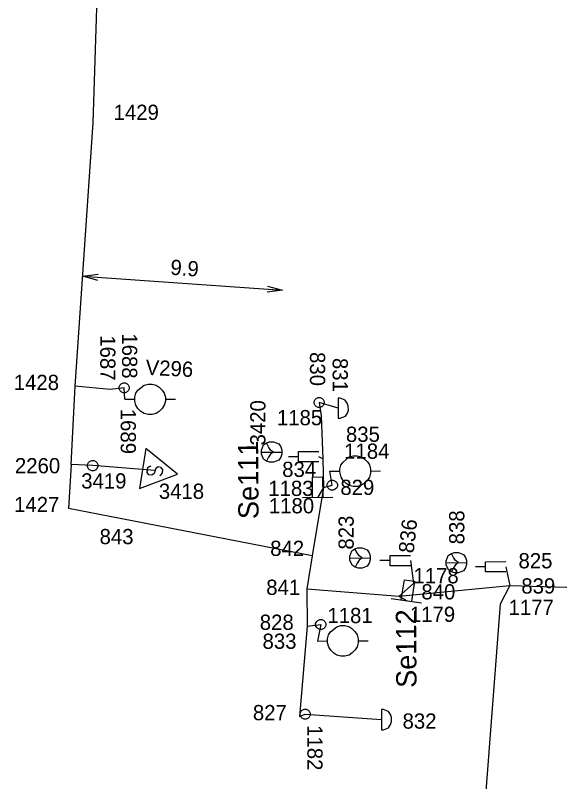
# Model space of a CAD drawing. Extents: x -535557 to -534097, y -1142175 to -1136716.
# Drawn here: x -534486.47 to -534459.64, y -1141039.91 to -1141002.16 of the extents above; entities that cross this region are included whole.
import ezdxf

# ---------------------------------------------------------------- set-up
doc = ezdxf.new("R2010")
doc.units = 0
doc.layers.add('Default', color=7, linetype='Continuous')
doc.layers.add('SS_SZDC', color=7, linetype='Continuous')

# ---------------------------------------------------------------- blocks, each defined once
blk = doc.blocks.new('POINT_DISPLAY')
at = {"layer": 'Default'}
blk.add_line((0, 0), (0, 0), dxfattribs=at)

msp = doc.modelspace()

# ---------------------------------------------------------------- linework, layer by layer
at = {"layer": 'SS_SZDC'}
for p, q in [((-534482.63, -1141007.459), (-534482.289, -1140996.2)), ((-534483.52, -1141020.42), (-534482.63, -1141007.459)), ((-534483.148, -1141015.012), (-534482.39, -1141014.914)), ((-534483.148, -1141015.012), (-534473.301, -1141015.695)), ((-534482.41, -1141015.213), (-534483.148, -1141015.012)), ((-534474.039, -1141015.493), (-534473.301, -1141015.695)), ((-534473.301, -1141015.695), (-534474.06, -1141015.793)), ((-534483.719, -1141024.29), (-534483.52, -1141020.42)), ((-534481.8, -1141020.59), (-534483.52, -1141020.42)), ((-534481.109, -1141020.51), (-534481.8, -1141020.59)), ((-534481.359, -1141020.46), (-534481.309, -1141020.36)), ((-534481.359, -1141020.56), (-534481.359, -1141020.46)), ((-534481.309, -1141020.66), (-534481.359, -1141020.56)), ((-534481.309, -1141020.36), (-534481.259, -1141020.31)), ((-534481.259, -1141020.31), (-534481.159, -1141020.26)), ((-534481.159, -1141020.26), (-534481.059, -1141020.26)), ((-534481.079, -1141021.069), (-534481.109, -1141020.51)), ((-534481.059, -1141020.26), (-534480.959, -1141020.31)), ((-534480.959, -1141020.31), (-534480.909, -1141020.36)), ((-534480.909, -1141020.36), (-534480.859, -1141020.46)), ((-534480.859, -1141020.56), (-534480.909, -1141020.66)), ((-534480.859, -1141020.46), (-534480.859, -1141020.56)), ((-534480.429, -1141020.619), (-534480.129, -1141020.369)), ((-534480.129, -1141020.369), (-534479.929, -1141020.319)), ((-534479.929, -1141020.319), (-534479.729, -1141020.319)), ((-534479.729, -1141020.319), (-534479.529, -1141020.369)), ((-534479.529, -1141020.369), (-534479.379, -1141020.469)), ((-534479.379, -1141020.469), (-534479.229, -1141020.619)), ((-534481.259, -1141020.71), (-534481.309, -1141020.66)), ((-534481.159, -1141020.76), (-534481.259, -1141020.71)), ((-534481.059, -1141020.76), (-534481.159, -1141020.76)), ((-534480.959, -1141020.71), (-534481.059, -1141020.76)), ((-534480.909, -1141020.66), (-534480.959, -1141020.71)), ((-534480.579, -1141020.969), (-534480.529, -1141020.769)), ((-534480.579, -1141021.069), (-534480.579, -1141020.969)), ((-534480.529, -1141020.769), (-534480.429, -1141020.619)), ((-534479.229, -1141020.619), (-534479.129, -1141020.769)), ((-534479.129, -1141020.769), (-534479.079, -1141020.969)), ((-534479.079, -1141020.969), (-534479.079, -1141021.169)), ((-534471.65, -1141021.029), (-534471.55, -1141020.979)), ((-534471.55, -1141020.979), (-534471.449, -1141020.979)), ((-534471.449, -1141020.979), (-534471.349, -1141021.029)), ((-534481.079, -1141021.069), (-534480.579, -1141021.069)), ((-534480.579, -1141021.169), (-534480.579, -1141021.069)), ((-534480.529, -1141021.369), (-534480.579, -1141021.169)), ((-534479.079, -1141021.169), (-534479.129, -1141021.369)), ((-534479.079, -1141021.069), (-534478.579, -1141021.069)), ((-534471.75, -1141021.179), (-534471.699, -1141021.079)), ((-534471.75, -1141021.279), (-534471.75, -1141021.179)), ((-534471.699, -1141021.379), (-534471.75, -1141021.279)), ((-534471.699, -1141021.079), (-534471.65, -1141021.029)), ((-534470.56, -1141021.51), (-534471.5, -1141021.229)), ((-534471.5, -1141021.229), (-534471.399, -1141021.899)), ((-534471.349, -1141021.029), (-534471.3, -1141021.079)), ((-534471.3, -1141021.079), (-534471.25, -1141021.179)), ((-534471.25, -1141021.279), (-534471.3, -1141021.379)), ((-534471.25, -1141021.179), (-534471.25, -1141021.279)), ((-534470.463, -1141021.009), (-534470.563, -1141021.01)), ((-534470.563, -1141021.01), (-534470.556, -1141022.009)), ((-534470.212, -1141021.107), (-534470.463, -1141021.009)), ((-534470.111, -1141021.257), (-534470.212, -1141021.107)), ((-534470.06, -1141021.406), (-534470.111, -1141021.257)), ((-534480.429, -1141021.519), (-534480.529, -1141021.369)), ((-534480.279, -1141021.669), (-534480.429, -1141021.519)), ((-534480.129, -1141021.769), (-534480.279, -1141021.669)), ((-534479.379, -1141021.669), (-534479.529, -1141021.769)), ((-534479.229, -1141021.519), (-534479.379, -1141021.669)), ((-534479.129, -1141021.369), (-534479.229, -1141021.519)), ((-534471.65, -1141021.429), (-534471.699, -1141021.379)), ((-534471.55, -1141021.479), (-534471.65, -1141021.429)), ((-534471.449, -1141021.479), (-534471.55, -1141021.479)), ((-534471.349, -1141021.429), (-534471.449, -1141021.479)), ((-534471.3, -1141021.379), (-534471.349, -1141021.429)), ((-534470.108, -1141021.757), (-534470.059, -1141021.606)), ((-534470.059, -1141021.606), (-534470.06, -1141021.406)), ((-534479.929, -1141021.819), (-534480.129, -1141021.769)), ((-534479.729, -1141021.819), (-534479.929, -1141021.819)), ((-534479.529, -1141021.769), (-534479.729, -1141021.819)), ((-534471.399, -1141021.899), (-534471.31, -1141024.01)), ((-534470.556, -1141022.009), (-534470.456, -1141022.009)), ((-534470.456, -1141022.009), (-534470.207, -1141021.907)), ((-534470.207, -1141021.907), (-534470.108, -1141021.757)), ((-534474.24, -1141023.32), (-534474.09, -1141023.22)), ((-534474.09, -1141023.22), (-534473.94, -1141023.17)), ((-534473.99, -1141023.42), (-534474.09, -1141023.22)), ((-534473.94, -1141023.17), (-534473.74, -1141023.17)), ((-534473.74, -1141023.17), (-534473.49, -1141023.27)), ((-534480.046, -1141023.498), (-534480.359, -1141025.473)), ((-534478.474, -1141024.759), (-534480.046, -1141023.498)), ((-534474.34, -1141023.57), (-534474.24, -1141023.32)), ((-534474.34, -1141023.77), (-534474.34, -1141023.57)), ((-534473.89, -1141023.57), (-534473.99, -1141023.42)), ((-534473.74, -1141023.67), (-534473.89, -1141023.57)), ((-534473.49, -1141023.27), (-534473.39, -1141023.42)), ((-534473.39, -1141023.42), (-534473.34, -1141023.57)), ((-534473.34, -1141023.57), (-534473.34, -1141023.77)), ((-534474.34, -1141023.67), (-534473.34, -1141023.67)), ((-534474.24, -1141024.02), (-534474.34, -1141023.77)), ((-534473.99, -1141023.92), (-534474.09, -1141024.12)), ((-534473.89, -1141023.77), (-534473.99, -1141023.92)), ((-534473.74, -1141023.67), (-534473.89, -1141023.77)), ((-534473.39, -1141023.92), (-534473.49, -1141024.07)), ((-534473.34, -1141023.77), (-534473.39, -1141023.92)), ((-534472.51, -1141023.899), (-534473.01, -1141023.899)), ((-534472.51, -1141024.149), (-534472.51, -1141023.649)), ((-534472.51, -1141023.649), (-534471.51, -1141023.649)), ((-534471.31, -1141024.01), (-534471.51, -1141023.899)), ((-534470.322, -1141024.165), (-534470.024, -1141023.913)), ((-534470.024, -1141023.913), (-534469.824, -1141023.862)), ((-534469.824, -1141023.862), (-534469.624, -1141023.861)), ((-534469.624, -1141023.861), (-534469.424, -1141023.909)), ((-534469.424, -1141023.909), (-534469.273, -1141024.008)), ((-534483.719, -1141024.29), (-534483.859, -1141026.459)), ((-534482.659, -1141024.34), (-534483.719, -1141024.29)), ((-534482.909, -1141024.29), (-534482.859, -1141024.19)), ((-534482.909, -1141024.39), (-534482.909, -1141024.29)), ((-534482.859, -1141024.19), (-534482.809, -1141024.14)), ((-534482.809, -1141024.14), (-534482.709, -1141024.09)), ((-534482.709, -1141024.09), (-534482.609, -1141024.09)), ((-534479.609, -1141024.579), (-534482.659, -1141024.34)), ((-534482.609, -1141024.09), (-534482.509, -1141024.14)), ((-534482.509, -1141024.14), (-534482.459, -1141024.19)), ((-534482.459, -1141024.19), (-534482.409, -1141024.29)), ((-534482.409, -1141024.29), (-534482.409, -1141024.39)), ((-534479.882, -1141024.384), (-534479.776, -1141024.351)), ((-534474.09, -1141024.12), (-534474.24, -1141024.02)), ((-534473.94, -1141024.17), (-534474.09, -1141024.12)), ((-534473.74, -1141024.17), (-534473.94, -1141024.17)), ((-534473.49, -1141024.07), (-534473.74, -1141024.17)), ((-534471.51, -1141024.149), (-534472.51, -1141024.149)), ((-534471.31, -1141024.01), (-534471.289, -1141025.409)), ((-534470.47, -1141024.516), (-534470.421, -1141024.316)), ((-534470.421, -1141024.316), (-534470.322, -1141024.165)), ((-534469.273, -1141024.008), (-534469.122, -1141024.157)), ((-534469.122, -1141024.157), (-534469.022, -1141024.307)), ((-534469.022, -1141024.307), (-534468.97, -1141024.506)), ((-534482.859, -1141024.49), (-534482.909, -1141024.39)), ((-534482.809, -1141024.54), (-534482.859, -1141024.49)), ((-534482.709, -1141024.59), (-534482.809, -1141024.54)), ((-534482.609, -1141024.59), (-534482.709, -1141024.59)), ((-534482.509, -1141024.54), (-534482.609, -1141024.59)), ((-534482.459, -1141024.49), (-534482.509, -1141024.54)), ((-534482.409, -1141024.39), (-534482.459, -1141024.49)), ((-534479.979, -1141024.673), (-534479.94, -1141024.426)), ((-534479.896, -1141024.787), (-534479.979, -1141024.673)), ((-534479.94, -1141024.426), (-534479.882, -1141024.384)), ((-534479.633, -1141024.728), (-534479.747, -1141024.811)), ((-534479.544, -1141024.489), (-534479.633, -1141024.728)), ((-534479.43, -1141024.405), (-534479.544, -1141024.489)), ((-534479.282, -1141024.429), (-534479.43, -1141024.405)), ((-534479.287, -1141024.782), (-534479.222, -1141024.691)), ((-534479.199, -1141024.543), (-534479.282, -1141024.429)), ((-534479.222, -1141024.691), (-534479.199, -1141024.543)), ((-534470.97, -1141024.62), (-534470.47, -1141024.616)), ((-534470.85, -1141025.299), (-534470.97, -1141024.62)), ((-534470.47, -1141024.616), (-534470.47, -1141024.516)), ((-534470.469, -1141024.716), (-534470.47, -1141024.616)), ((-534470.418, -1141024.916), (-534470.469, -1141024.716)), ((-534468.969, -1141024.706), (-534469.018, -1141024.907)), ((-534468.97, -1141024.506), (-534468.969, -1141024.706)), ((-534468.97, -1141024.606), (-534468.47, -1141024.603)), ((-534480.359, -1141025.473), (-534478.474, -1141024.759)), ((-534479.747, -1141024.811), (-534479.896, -1141024.787)), ((-534479.344, -1141024.824), (-534479.287, -1141024.782)), ((-534471.826, -1141024.901), (-534471.326, -1141024.898)), ((-534471.819, -1141025.901), (-534471.826, -1141024.901)), ((-534471.326, -1141024.898), (-534471.32, -1141025.898)), ((-534471.05, -1141025.149), (-534471, -1141025.099)), ((-534471, -1141025.099), (-534470.9, -1141025.049)), ((-534470.9, -1141025.049), (-534470.8, -1141025.049)), ((-534470.8, -1141025.049), (-534470.7, -1141025.099)), ((-534470.7, -1141025.099), (-534470.65, -1141025.149)), ((-534470.317, -1141025.065), (-534470.418, -1141024.916)), ((-534470.166, -1141025.214), (-534470.317, -1141025.065)), ((-534469.117, -1141025.057), (-534469.266, -1141025.208)), ((-534469.018, -1141024.907), (-534469.117, -1141025.057)), ((-534471.289, -1141025.409), (-534471.84, -1141028.78)), ((-534471.289, -1141025.409), (-534471.569, -1141025.899)), ((-534471.289, -1141025.409), (-534470.85, -1141025.299)), ((-534471.1, -1141025.249), (-534471.05, -1141025.149)), ((-534471.1, -1141025.349), (-534471.1, -1141025.249)), ((-534471.05, -1141025.449), (-534471.1, -1141025.349)), ((-534471, -1141025.499), (-534471.05, -1141025.449)), ((-534470.9, -1141025.549), (-534471, -1141025.499)), ((-534470.7, -1141025.499), (-534470.8, -1141025.549)), ((-534470.65, -1141025.449), (-534470.7, -1141025.499)), ((-534470.65, -1141025.149), (-534470.6, -1141025.249)), ((-534470.6, -1141025.349), (-534470.65, -1141025.449)), ((-534470.6, -1141025.249), (-534470.6, -1141025.349)), ((-534470.015, -1141025.313), (-534470.166, -1141025.214)), ((-534469.815, -1141025.362), (-534470.015, -1141025.313)), ((-534469.615, -1141025.361), (-534469.815, -1141025.362)), ((-534469.415, -1141025.309), (-534469.615, -1141025.361)), ((-534469.266, -1141025.208), (-534469.415, -1141025.309)), ((-534470.8, -1141025.549), (-534470.9, -1141025.549)), ((-534472.319, -1141025.904), (-534470.82, -1141025.895)), ((-534481.819, -1141026.85), (-534483.859, -1141026.459)), ((-534471.84, -1141028.78), (-534481.819, -1141026.85)), ((-534469.882, -1141028.542), (-534469.732, -1141028.441)), ((-534469.732, -1141028.441), (-534469.583, -1141028.39)), ((-534469.631, -1141028.64), (-534469.732, -1141028.441)), ((-534469.583, -1141028.39), (-534469.383, -1141028.389)), ((-534469.383, -1141028.389), (-534469.132, -1141028.487)), ((-534469.132, -1141028.487), (-534469.031, -1141028.637)), ((-534471.84, -1141028.78), (-534472.1, -1141030.409)), ((-534469.98, -1141028.793), (-534469.882, -1141028.542)), ((-534469.979, -1141028.993), (-534469.98, -1141028.793)), ((-534469.979, -1141028.893), (-534468.98, -1141028.886)), ((-534469.53, -1141028.79), (-534469.631, -1141028.64)), ((-534469.38, -1141028.889), (-534469.53, -1141028.79)), ((-534469.38, -1141028.889), (-534469.529, -1141028.99)), ((-534469.031, -1141028.637), (-534468.98, -1141028.786)), ((-534468.98, -1141028.786), (-534468.979, -1141028.986)), ((-534468, -1141029.27), (-534468, -1141028.77)), ((-534468, -1141028.77), (-534467, -1141028.77)), ((-534465.23, -1141029.023), (-534465.132, -1141028.772)), ((-534465.132, -1141028.772), (-534464.982, -1141028.671)), ((-534464.982, -1141028.671), (-534464.833, -1141028.62)), ((-534464.881, -1141028.87), (-534464.982, -1141028.671)), ((-534464.78, -1141029.02), (-534464.881, -1141028.87)), ((-534464.833, -1141028.62), (-534464.633, -1141028.619)), ((-534464.633, -1141028.619), (-534464.382, -1141028.717)), ((-534464.382, -1141028.717), (-534464.281, -1141028.867)), ((-534464.281, -1141028.867), (-534464.23, -1141029.016)), ((-534469.877, -1141029.242), (-534469.979, -1141028.993)), ((-534469.727, -1141029.341), (-534469.877, -1141029.242)), ((-534469.628, -1141029.14), (-534469.727, -1141029.341)), ((-534469.529, -1141028.99), (-534469.628, -1141029.14)), ((-534469.028, -1141029.137), (-534469.127, -1141029.287)), ((-534468.979, -1141028.986), (-534469.028, -1141029.137)), ((-534468, -1141029.02), (-534468.5, -1141029.02)), ((-534467, -1141029.27), (-534468, -1141029.27)), ((-534467, -1141029.02), (-534466.85, -1141030.139)), ((-534465.229, -1141029.223), (-534465.23, -1141029.023)), ((-534465.229, -1141029.123), (-534464.23, -1141029.116)), ((-534465.127, -1141029.472), (-534465.229, -1141029.223)), ((-534464.779, -1141029.22), (-534464.878, -1141029.37)), ((-534464.63, -1141029.119), (-534464.78, -1141029.02)), ((-534464.63, -1141029.119), (-534464.779, -1141029.22)), ((-534464.229, -1141029.216), (-534464.278, -1141029.367)), ((-534464.23, -1141029.016), (-534464.229, -1141029.216)), ((-534463.301, -1141029.076), (-534462.301, -1141029.07)), ((-534463.298, -1141029.576), (-534463.301, -1141029.076)), ((-534469.576, -1141029.39), (-534469.727, -1141029.341)), ((-534469.376, -1141029.389), (-534469.576, -1141029.39)), ((-534469.127, -1141029.287), (-534469.376, -1141029.389)), ((-534464.977, -1141029.571), (-534465.127, -1141029.472)), ((-534464.878, -1141029.37), (-534464.977, -1141029.571)), ((-534464.826, -1141029.62), (-534464.977, -1141029.571)), ((-534464.626, -1141029.619), (-534464.826, -1141029.62)), ((-534464.377, -1141029.517), (-534464.626, -1141029.619)), ((-534464.278, -1141029.367), (-534464.377, -1141029.517)), ((-534463.299, -1141029.326), (-534463.799, -1141029.329)), ((-534462.298, -1141029.569), (-534463.298, -1141029.576)), ((-534462.3, -1141029.319), (-534462.1, -1141030.239)), ((-534467.447, -1141030.952), (-534467.297, -1141029.963)), ((-534467.297, -1141029.963), (-534466.802, -1141030.038)), ((-534466.802, -1141030.038), (-534466.952, -1141031.027)), ((-534472.1, -1141030.409), (-534467.56, -1141030.77)), ((-534472.1, -1141030.409), (-534472.09, -1141032.25)), ((-534466.85, -1141030.139), (-534467.56, -1141030.77)), ((-534467.56, -1141030.77), (-534462.1, -1141030.239)), ((-534462.1, -1141030.239), (-534462.579, -1141031.17)), ((-534462.1, -1141030.239), (-534451.649, -1141030.549)), ((-534467.56, -1141030.77), (-534467.199, -1141030.989)), ((-534467.941, -1141030.877), (-534466.458, -1141031.102)), ((-534462.579, -1141031.17), (-534464.55, -1141056.84)), ((-534471.57, -1141031.97), (-534471.47, -1141031.92)), ((-534471.47, -1141031.92), (-534471.37, -1141031.92)), ((-534471.37, -1141031.92), (-534471.27, -1141031.97)), ((-534472.09, -1141032.25), (-534472.46, -1141036.7)), ((-534472.09, -1141032.25), (-534471.42, -1141032.17)), ((-534471.67, -1141032.12), (-534471.62, -1141032.02)), ((-534471.67, -1141032.22), (-534471.67, -1141032.12)), ((-534471.62, -1141032.32), (-534471.67, -1141032.22)), ((-534471.62, -1141032.02), (-534471.57, -1141031.97)), ((-534471.42, -1141032.17), (-534471.579, -1141032.979)), ((-534471.27, -1141031.97), (-534471.22, -1141032.02)), ((-534471.22, -1141032.02), (-534471.17, -1141032.12)), ((-534471.17, -1141032.22), (-534471.22, -1141032.32)), ((-534471.17, -1141032.12), (-534471.17, -1141032.22)), ((-534470.932, -1141032.525), (-534470.634, -1141032.273)), ((-534470.634, -1141032.273), (-534470.434, -1141032.222)), ((-534470.434, -1141032.222), (-534470.234, -1141032.221)), ((-534470.234, -1141032.221), (-534470.034, -1141032.269)), ((-534470.034, -1141032.269), (-534469.883, -1141032.368)), ((-534471.57, -1141032.37), (-534471.62, -1141032.32)), ((-534471.47, -1141032.42), (-534471.57, -1141032.37)), ((-534471.37, -1141032.42), (-534471.47, -1141032.42)), ((-534471.27, -1141032.37), (-534471.37, -1141032.42)), ((-534471.22, -1141032.32), (-534471.27, -1141032.37)), ((-534471.08, -1141032.876), (-534471.031, -1141032.676)), ((-534471.031, -1141032.676), (-534470.932, -1141032.525)), ((-534469.883, -1141032.368), (-534469.732, -1141032.517)), ((-534469.732, -1141032.517), (-534469.632, -1141032.667)), ((-534469.632, -1141032.667), (-534469.58, -1141032.866)), ((-534471.579, -1141032.979), (-534471.08, -1141032.976)), ((-534471.08, -1141032.976), (-534471.08, -1141032.876)), ((-534471.079, -1141033.076), (-534471.08, -1141032.976)), ((-534469.58, -1141032.866), (-534469.579, -1141033.066)), ((-534469.58, -1141032.966), (-534469.08, -1141032.963)), ((-534471.028, -1141033.276), (-534471.079, -1141033.076)), ((-534470.927, -1141033.425), (-534471.028, -1141033.276)), ((-534470.776, -1141033.574), (-534470.927, -1141033.425)), ((-534469.727, -1141033.417), (-534469.876, -1141033.568)), ((-534469.628, -1141033.267), (-534469.727, -1141033.417)), ((-534469.579, -1141033.066), (-534469.628, -1141033.267)), ((-534470.625, -1141033.673), (-534470.776, -1141033.574)), ((-534470.425, -1141033.722), (-534470.625, -1141033.673)), ((-534470.225, -1141033.721), (-534470.425, -1141033.722)), ((-534470.025, -1141033.669), (-534470.225, -1141033.721)), ((-534469.876, -1141033.568), (-534470.025, -1141033.669)), ((-534472.439, -1141036.529), (-534472.389, -1141036.429)), ((-534472.389, -1141036.429), (-534472.339, -1141036.379)), ((-534472.339, -1141036.379), (-534472.239, -1141036.329)), ((-534472.239, -1141036.329), (-534472.139, -1141036.329)), ((-534472.139, -1141036.329), (-534472.039, -1141036.379)), ((-534472.039, -1141036.379), (-534471.989, -1141036.429)), ((-534471.989, -1141036.429), (-534471.939, -1141036.529)), ((-534468.33, -1141036.35), (-534468.43, -1141036.35)), ((-534468.43, -1141036.35), (-534468.43, -1141037.35)), ((-534468.08, -1141036.45), (-534468.33, -1141036.35)), ((-534467.98, -1141036.6), (-534468.08, -1141036.45)), ((-534472.46, -1141036.7), (-534472.189, -1141036.579)), ((-534472.439, -1141036.629), (-534472.439, -1141036.529)), ((-534472.389, -1141036.729), (-534472.439, -1141036.629)), ((-534472.339, -1141036.779), (-534472.389, -1141036.729)), ((-534472.239, -1141036.829), (-534472.339, -1141036.779)), ((-534472.139, -1141036.829), (-534472.239, -1141036.829)), ((-534472.189, -1141036.579), (-534468.43, -1141036.85)), ((-534472.039, -1141036.779), (-534472.139, -1141036.829)), ((-534471.989, -1141036.729), (-534472.039, -1141036.779)), ((-534471.939, -1141036.629), (-534471.989, -1141036.729)), ((-534471.939, -1141036.529), (-534471.939, -1141036.629)), ((-534467.93, -1141036.75), (-534467.98, -1141036.6)), ((-534467.93, -1141036.95), (-534467.93, -1141036.75)), ((-534468.08, -1141037.25), (-534467.98, -1141037.1)), ((-534467.98, -1141037.1), (-534467.93, -1141036.95)), ((-534468.43, -1141037.35), (-534468.33, -1141037.35)), ((-534468.33, -1141037.35), (-534468.08, -1141037.25))]:
    msp.add_line(p, q, dxfattribs=at)

# ---------------------------------------------------------------- block references
for p in [(-534482.63, -1141007.459), (-534483.52, -1141020.42), (-534481.8, -1141020.59), (-534481.109, -1141020.51), (-534481.109, -1141020.51), (-534481.079, -1141021.069), (-534471.5, -1141021.229), (-534471.5, -1141021.229), (-534470.56, -1141021.51), (-534471.399, -1141021.899), (-534473.84, -1141023.67), (-534471.51, -1141023.899), (-534483.719, -1141024.29), (-534482.659, -1141024.34), (-534482.659, -1141024.34), (-534471.31, -1141024.01), (-534479.609, -1141024.579), (-534470.97, -1141024.62), (-534471.289, -1141025.409), (-534470.85, -1141025.299), (-534470.85, -1141025.299), (-534471.569, -1141025.899), (-534483.859, -1141026.459), (-534481.819, -1141026.85), (-534471.84, -1141028.78), (-534469.479, -1141028.889), (-534467, -1141029.02), (-534464.729, -1141029.12), (-534462.3, -1141029.319), (-534472.1, -1141030.409), (-534466.85, -1141030.139), (-534462.1, -1141030.239), (-534467.56, -1141030.77), (-534467.199, -1141030.989), (-534462.579, -1141031.17), (-534472.09, -1141032.25), (-534471.42, -1141032.17), (-534471.42, -1141032.17), (-534471.579, -1141032.979), (-534472.46, -1141036.7), (-534472.189, -1141036.579), (-534472.189, -1141036.579), (-534468.43, -1141036.85)]:
    msp.add_blockref('POINT_DISPLAY', p, dxfattribs=at)

# ---------------------------------------------------------------- texts
for s, p in [('1429', (-534481.63, -1141007.309)), ('1428', (-534486.55, -1141020.616)), ('1185', (-534473.579, -1141022.351)), ('835', (-534470.177, -1141023.17)), ('1184', (-534470.265, -1141024.001)), ('2260', (-534486.493, -1141024.717)), ('834', (-534473.319, -1141024.898)), ('3419', (-534483.226, -1141025.468)), ('1183', (-534474.005, -1141025.834)), ('829', (-534470.452, -1141025.784)), ('3418', (-534479.4, -1141025.978)), ('1427', (-534486.535, -1141026.631)), ('1180', (-534473.976, -1141026.69)), ('843', (-534482.32, -1141028.209)), ('842', (-534473.911, -1141028.788)), ('825', (-534461.671, -1141029.399)), ('1178', (-534466.85, -1141030.139)), ('841', (-534474.105, -1141030.707)), ('839', (-534461.533, -1141030.641)), ('840', (-534466.458, -1141030.93)), ('1177', (-534462.162, -1141031.7)), ('1181', (-534471.09, -1141032.099)), ('1179', (-534467.025, -1141032.037)), ('828', (-534474.424, -1141032.43)), ('833', (-534474.288, -1141033.365)), ('827', (-534474.764, -1141036.881)), ('832', (-534467.387, -1141037.297))]:
    msp.add_text(s, height=0.75, dxfattribs=at).set_placement(p)
for s, height, rotation, p in [('9.9', 0.75, 356.0319, (-534478.849, -1141014.934)), ('1688', 0.75, 270, (-534481.213, -1141017.823)), ('1687', 0.75, 270, (-534482.289, -1141017.918)), ('830', 0.75, 270, (-534471.951, -1141018.744)), ('831', 0.75, 270, (-534470.833, -1141019.035)), ('V296', 0.75, 357.3, (-534480.065, -1141019.867)), ('3420', 0.75, 90, (-534474.145, -1141023.346)), ('1689', 0.75, 270, (-534481.28, -1141021.538)), ('Se111', 1, 90.3756, (-534474.481, -1141026.971)), ('838', 0.75, 90, (-534464.34, -1141028.216)), ('823', 0.75, 90, (-534469.795, -1141028.475)), ('836', 0.75, 83.7, (-534466.841, -1141028.678)), ('Se112', 1, 90.3756, (-534466.696, -1141035.284)), ('1182', 0.75, 270, (-534472.08, -1141037.123))]:
    msp.add_text(s, height=height, rotation=rotation, dxfattribs=at).set_placement(p)

doc.saveas('drawing.dxf')
